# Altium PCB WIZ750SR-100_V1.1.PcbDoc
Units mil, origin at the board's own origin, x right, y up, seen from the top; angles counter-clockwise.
Board outline 1968.5 x 1181.1 mil, 4 copper layers (Top Layer, Internal Plane 1, Internal Plane 2, Bottom Layer); 76 components, 81 nets, 315 pads, 135 vias.
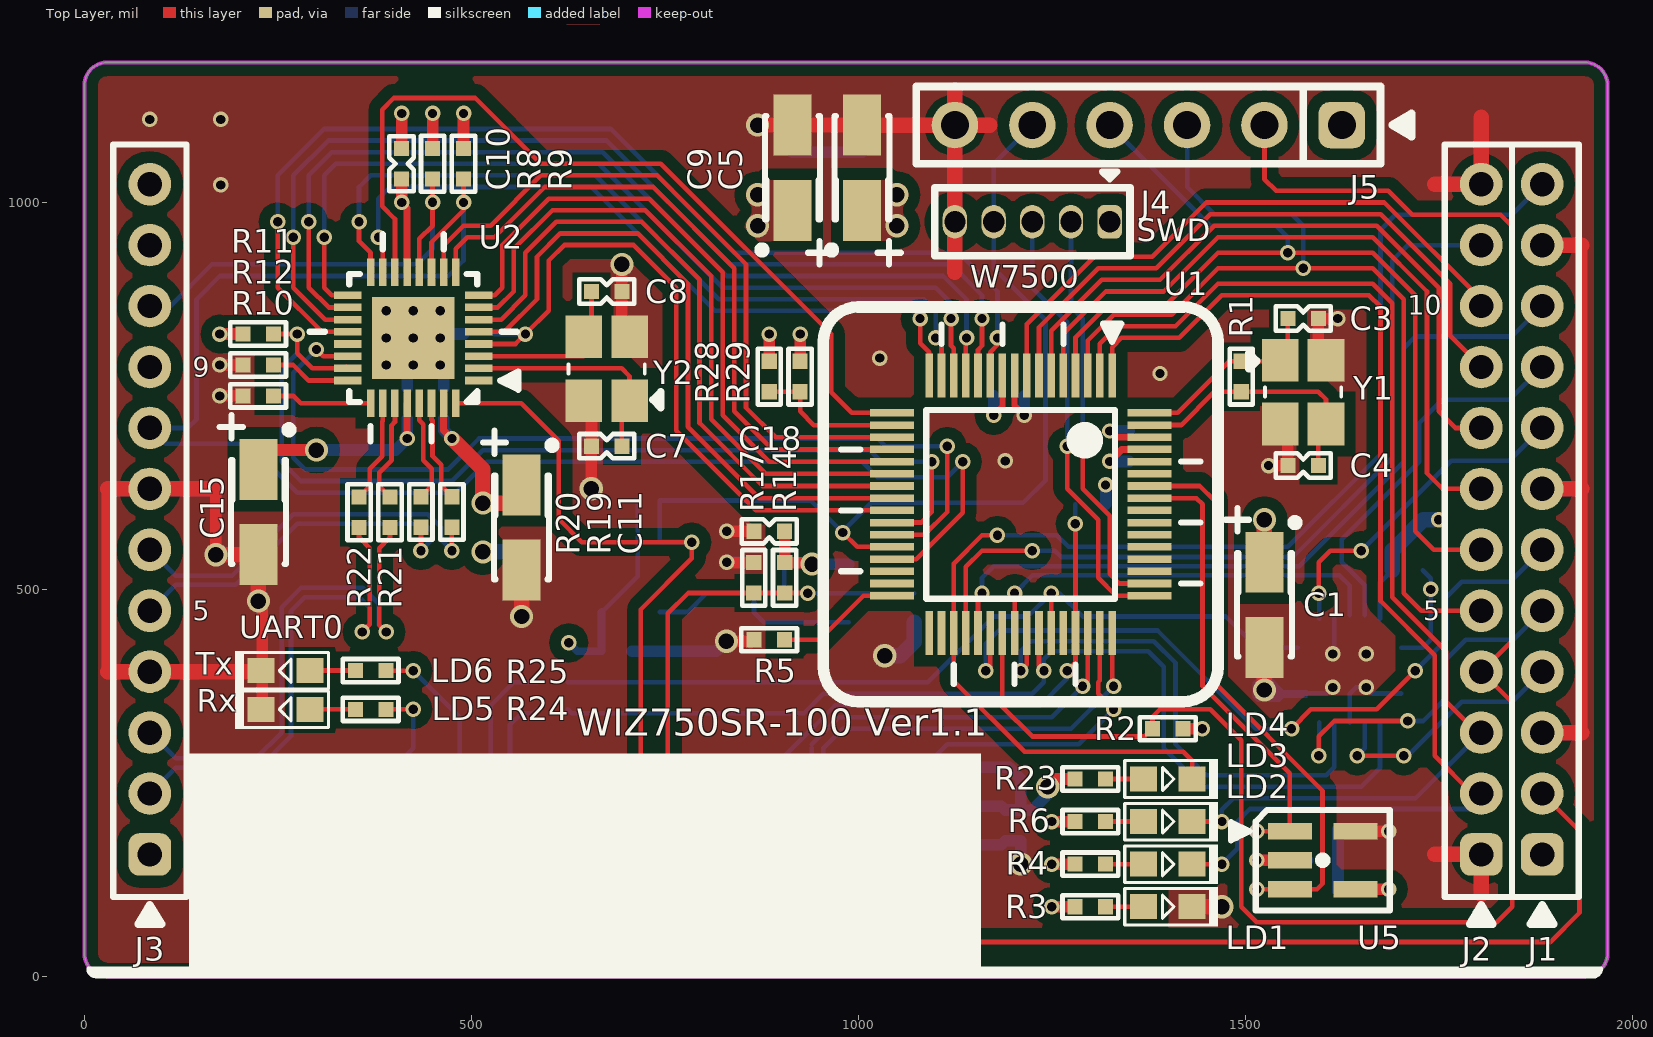
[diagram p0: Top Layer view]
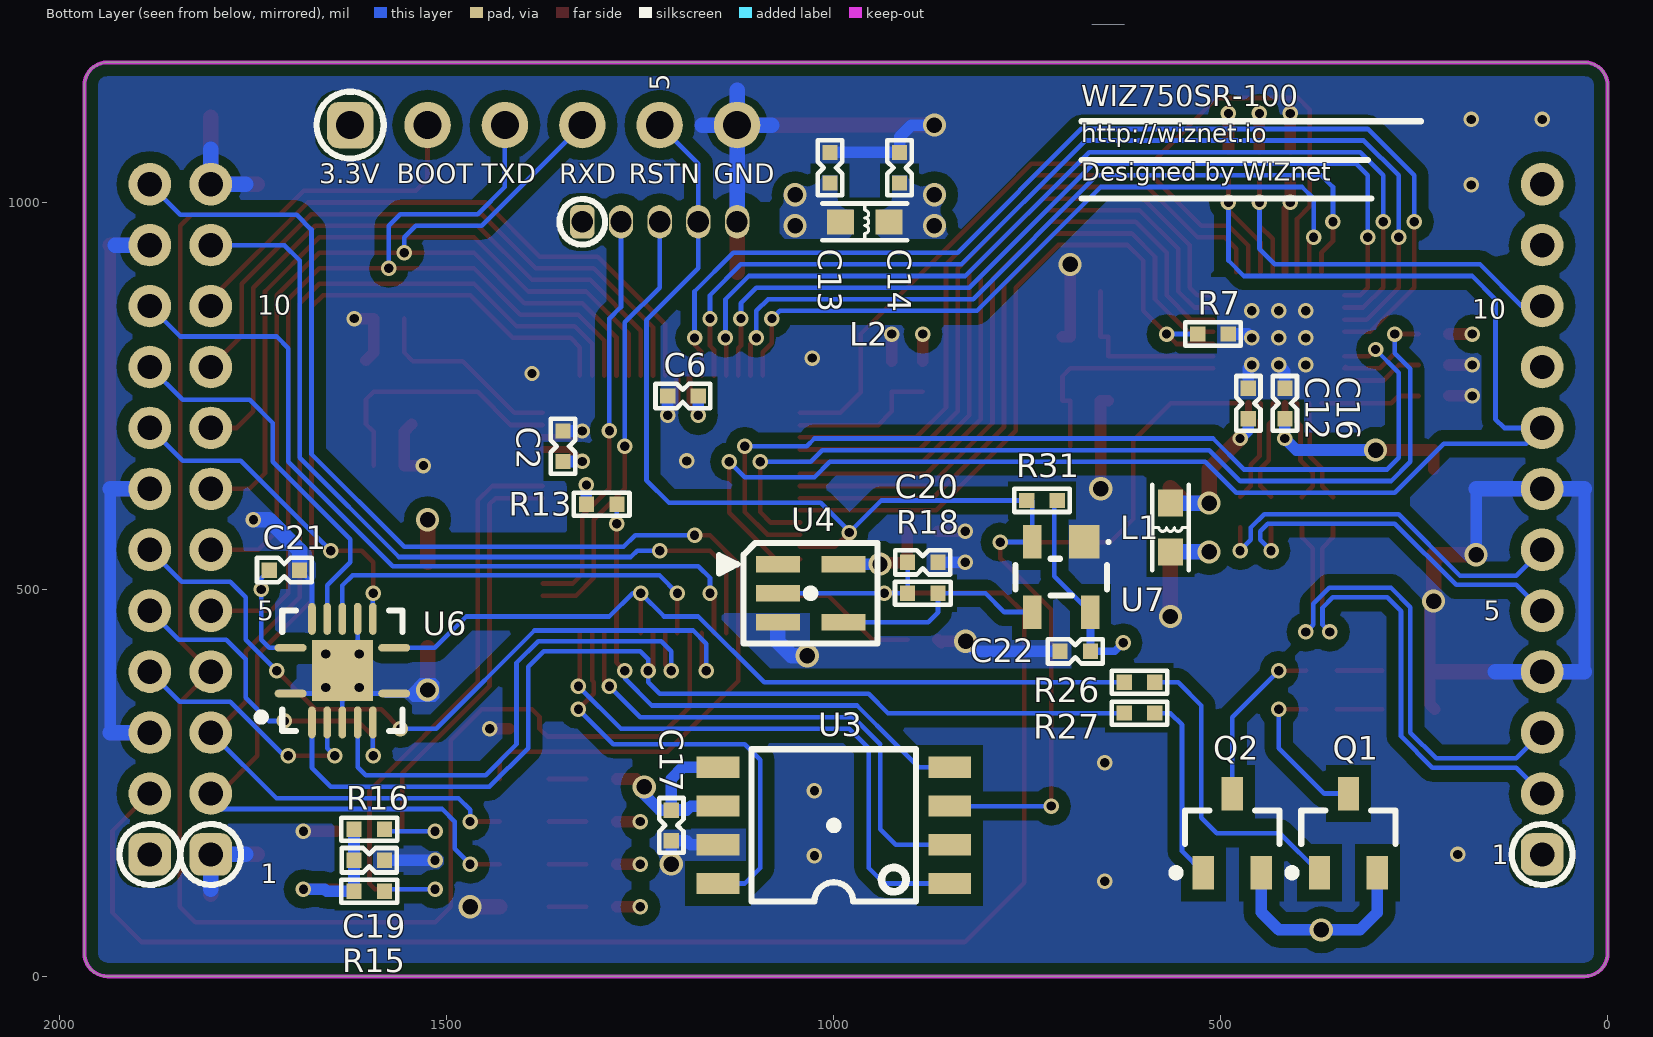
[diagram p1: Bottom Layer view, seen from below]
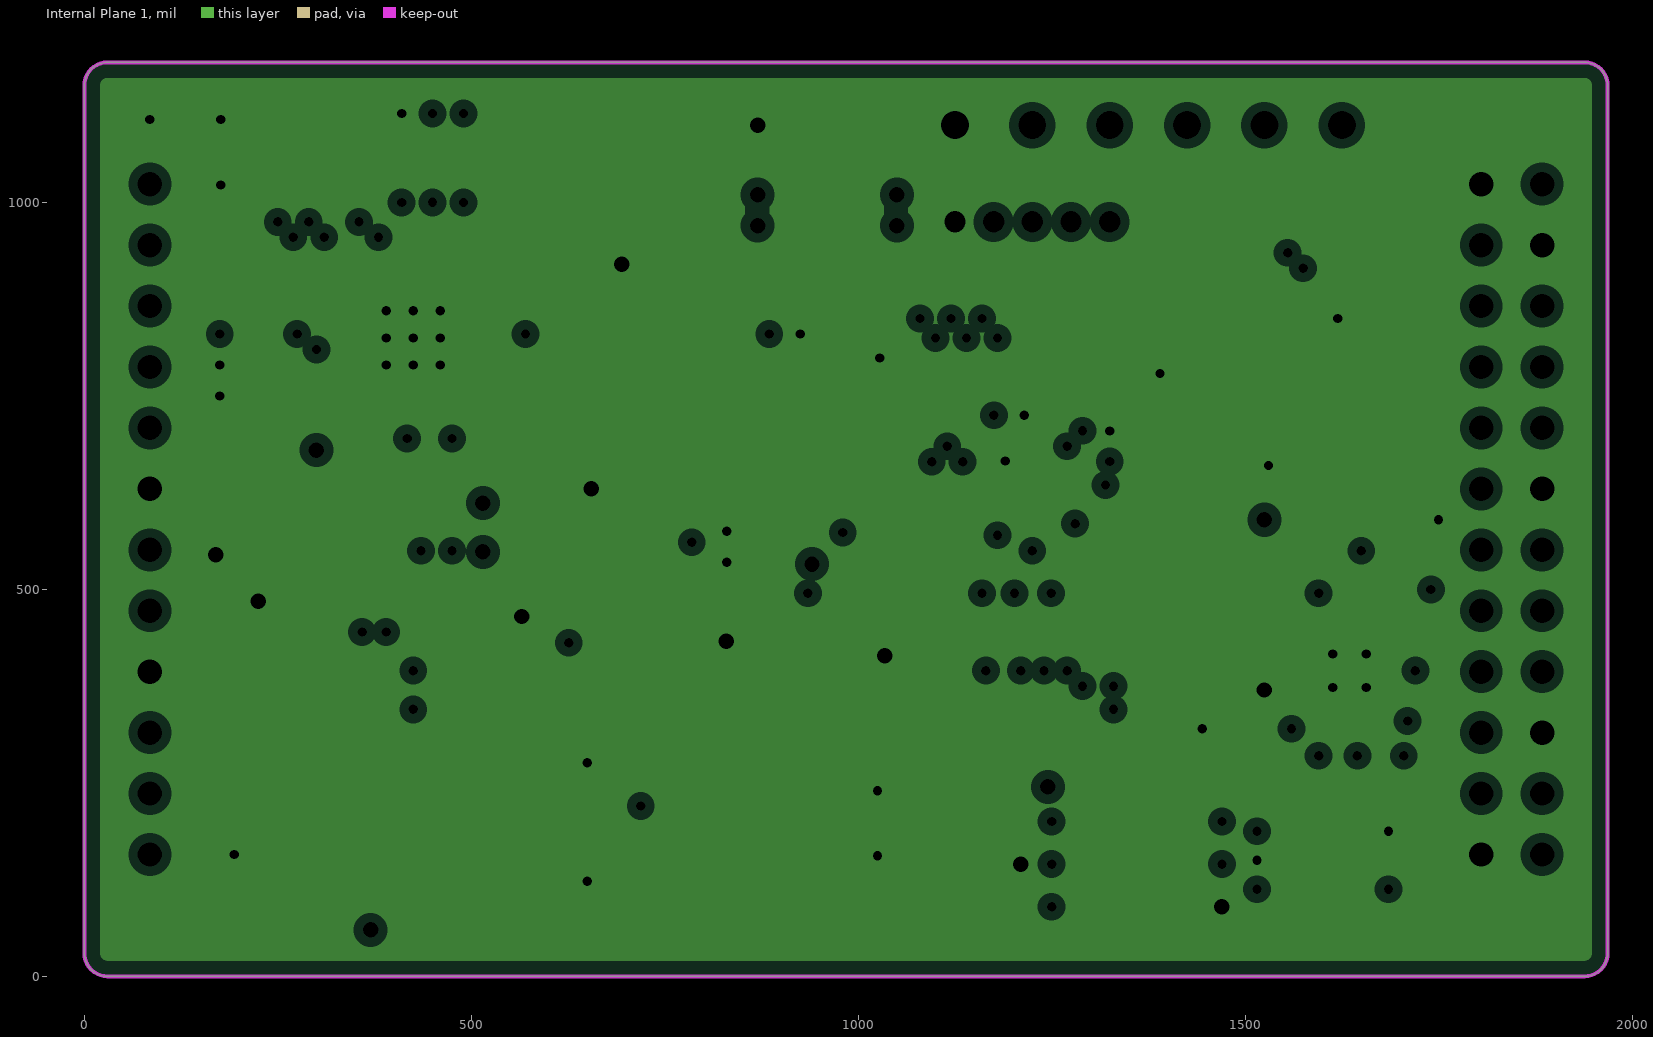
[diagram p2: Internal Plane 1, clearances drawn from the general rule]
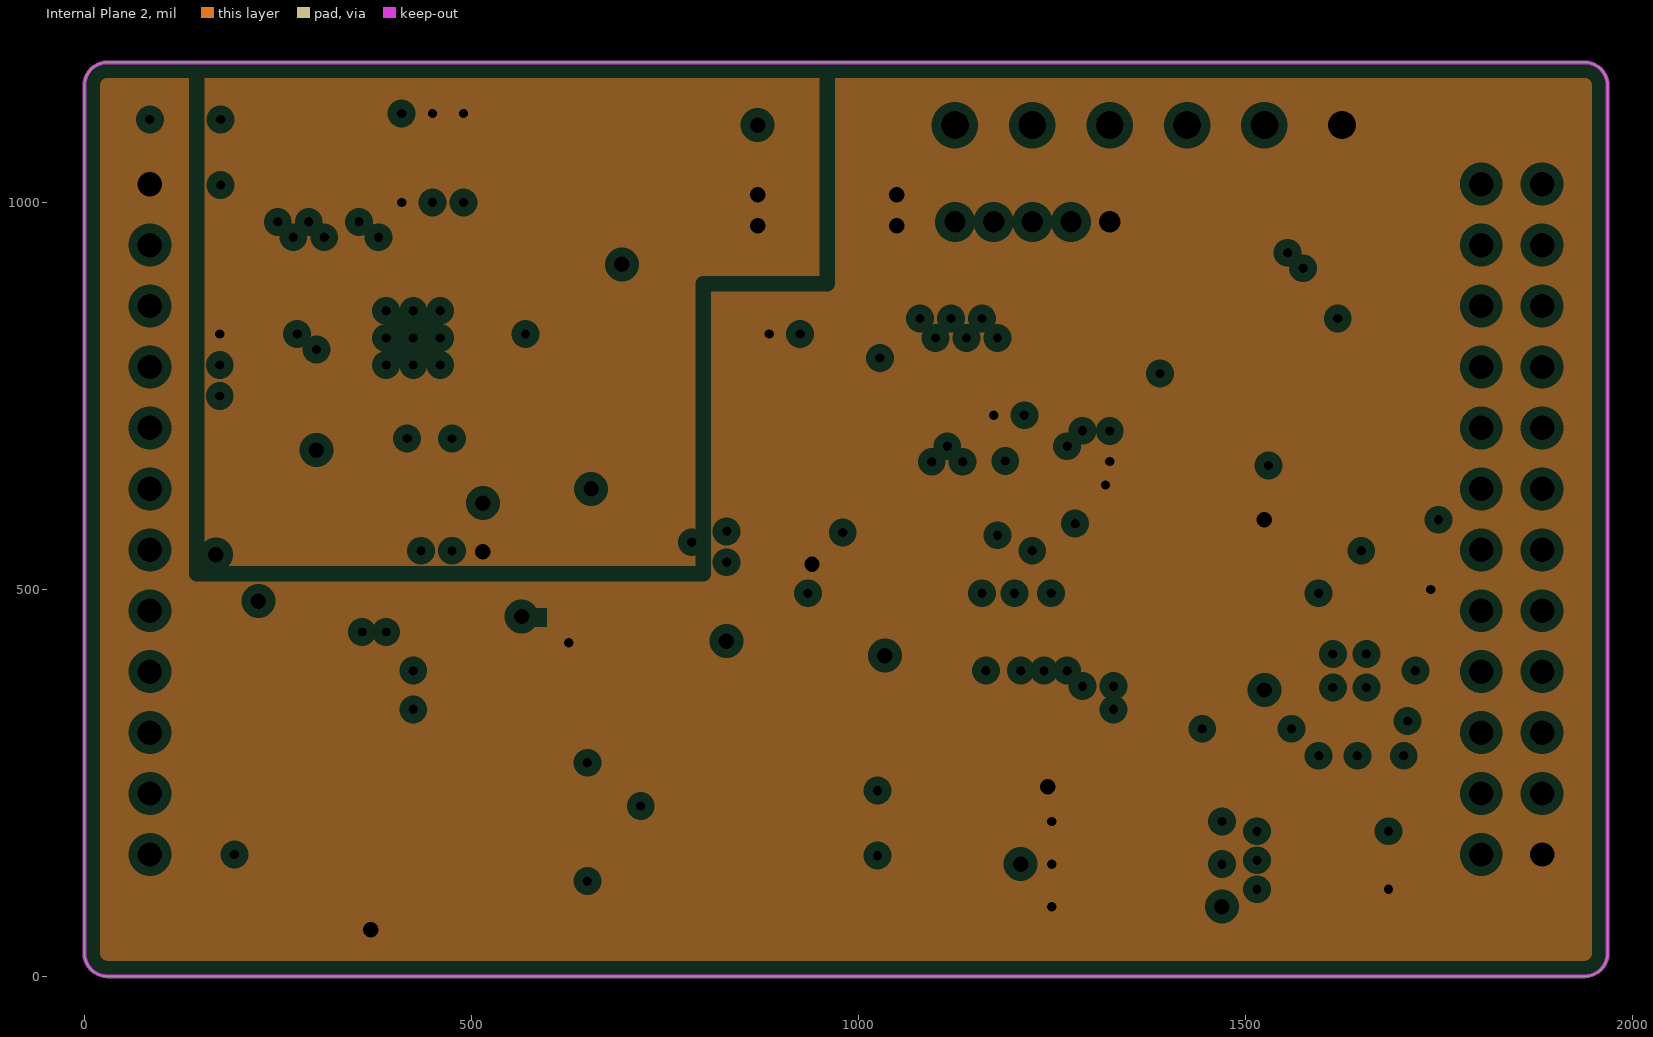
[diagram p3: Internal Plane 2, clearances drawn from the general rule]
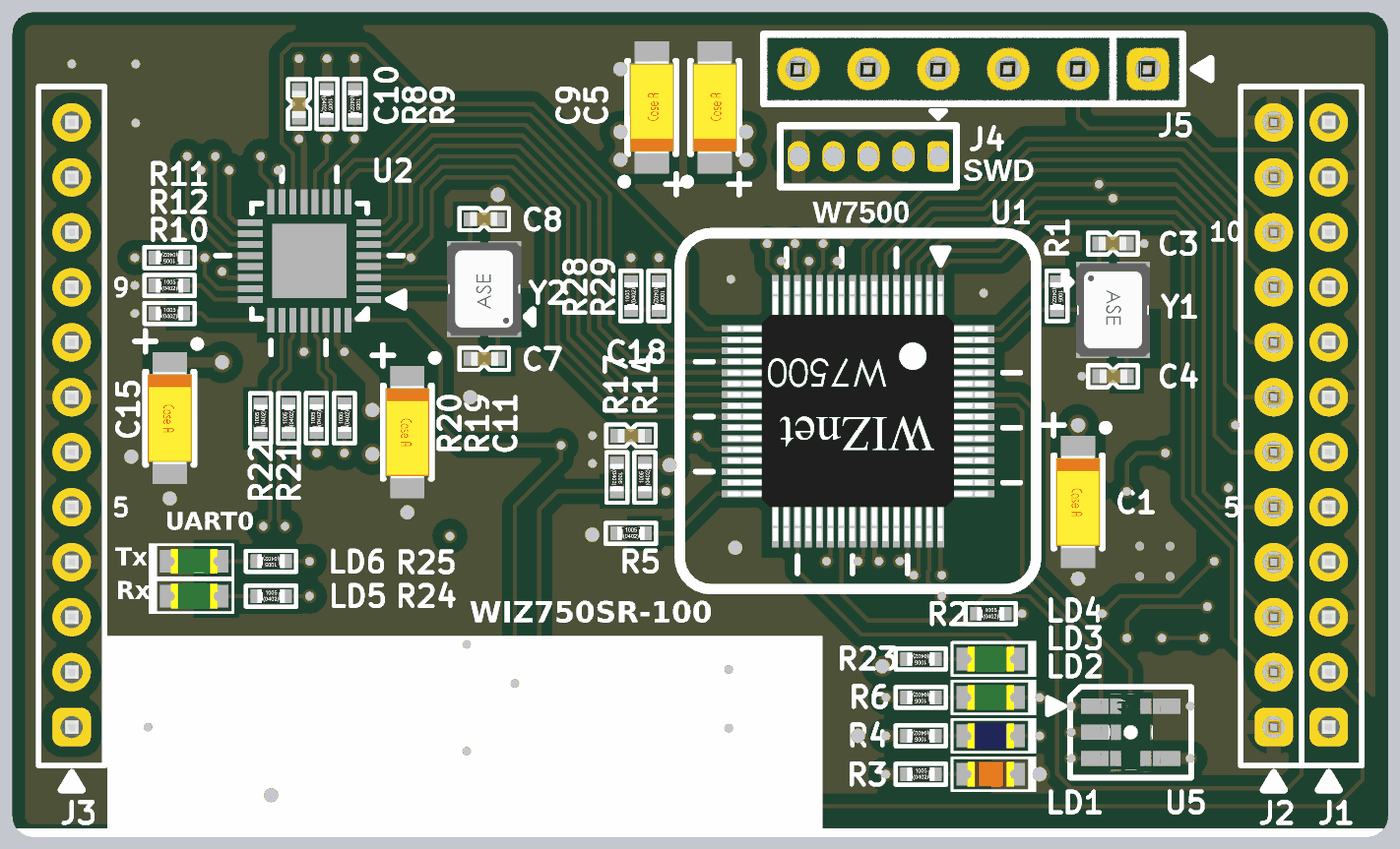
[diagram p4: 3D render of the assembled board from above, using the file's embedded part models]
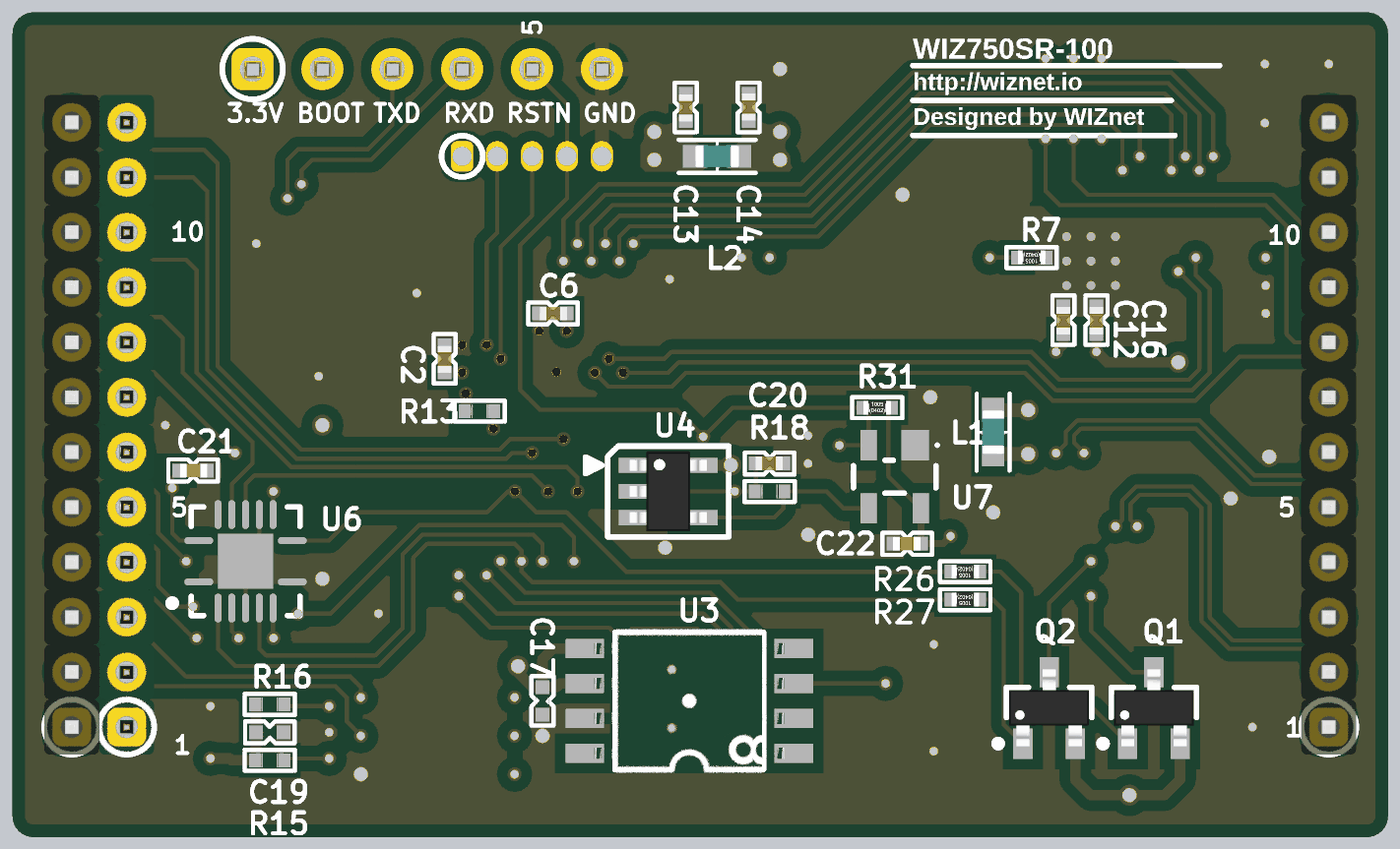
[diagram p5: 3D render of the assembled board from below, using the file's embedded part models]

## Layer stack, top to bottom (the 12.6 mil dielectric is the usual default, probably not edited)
Top Solder: solder mask 0.4, Solder Resist, Dk 3.5
Top Layer: signal copper 1.4
Dielectric1: core 12.6, FR-4, Dk 4.8
Internal Plane 1: plane copper 1.4, net GND
Dielectric5: prepreg 12.6, FR-4, Dk 4.8
Internal Plane 2: plane copper 1.4, net (Multiple Nets)
Dielectric6: core 12.6, FR-4, Dk 4.8
Bottom Layer: signal copper 1.4
Bottom Solder: solder mask 0.4, Solder Resist, Dk 3.5

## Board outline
0,30 0,1151.1 cw(c30,1151.1) 30,1181.1 1938.5,1181.1 cw(c1938.5,1151.1) 1968.5,1151.1 1968.5,30 cw(c1938.5,30) 1938.5,0 30,0 cw(c30,30)

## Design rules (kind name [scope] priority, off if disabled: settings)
Clearance [All] p1: gap=5.91 except(15: Arc-Poly Track-Poly SMDPad-Poly THPad-Poly Via-Poly Fill-Poly Poly-Poly Poly-Region)
DiffPairsRouting [All] p1: maxlimit=6 minlimit=6 mostfreqgap=6 toplayer_minwidth=6 toplayer_maxwidth=6 toplayer_prefwidth=6 bottomlayer_minwidth=6 bottomlayer_maxwidth=6 bottomlayer_prefwidth=6 maxuncoupledlength=600
HoleSize [All] p1: absolutevalues=TRUE maxlimit=160 minlimit=1 maxpercent=80.000 minpercent=20.000
PlaneClearance [All] p1: clearance=12
PlaneConnect [All] p1: planeconnectstyle=Direct reliefexpansion=20 reliefentries=4 reliefconductorwidth=10 reliefairgap=10
PolygonConnect PolygonConnect_2 [IsPad vs IsNamedPolygon('Top Layer-GND') Or  IsNamedPolygon('Bottom Layer-GND')] p1: connectstyle=Relief reliefconductorwidth=15 reliefentries=4 polygonreliefangle="90 Angle" airgapwidth=15
PolygonConnect PolygonConnect_1 [IsVia] p2: connectstyle=Direct reliefconductorwidth=10 reliefentries=4 polygonreliefangle="90 Angle" airgapwidth=10
PolygonConnect [All] p3: connectstyle=Direct reliefconductorwidth=10 reliefentries=4 polygonreliefangle="90 Angle" airgapwidth=10
RoutingVias [All] p1: holewidth=12 width=20 viastyle="Through Hole" minholewidth=12 minwidth=20 maxholewidth=20 maxwidth=30
SolderMaskExpansion [All] p1: expansion=0
Width [All] p1: maxlimit=20 minlimit=4 preferedwidth=5.98 minimp=50.000000 maximp=50.000000 favimp=50.000000
26 further rules are at their usual default settings.

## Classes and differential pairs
component class 1.WIZ750SR-100_W7500: C1 C2 C3 C4 C5 C6 LD1 LD2 LD3 LD4 LD5 LD6 Q1 Q2 R1 R2 R3 R4 R5 R6 R23 R24 R25 R26 R27 R28 R29 U1 Y1
component class 2.WIZ750SR_Transceiver: LD1 LD2 R41
differential pair MDI0_T: +MDI_T_P -MDI_T_N
differential pair MDI0_R: +MDI_R_P -MDI_R_N
differential pair MDI0_R: +MDI0_R_P -MDI0_R_N
differential pair MDI0_T: +MDI0_T_P -MDI0_T_N

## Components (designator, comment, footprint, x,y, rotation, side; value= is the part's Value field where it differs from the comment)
C1 "10uF/16V" "CAP-A Size" 1525,480 r270 top
C2 "1uF" CAP-0402#1 1350,685 r270 bottom
C3 "30pF" CAP-0402#1 1575,850 r180 top
C4 "30pF" CAP-0402#1 1575,660 r0 top
C5 "10uF/16V" "CAP-A Size" 1005,1045 r90 top
C6 "1uF" CAP-0402#1 1195,750 r180 bottom
C7 "27pF" CAP-0402#1 675,685 r0 top
C8 "27pF" CAP-0402#1 675,885 r180 top
C9 "10uF/16V" "CAP-A Size" 915,1045 r90 top
C10 "0.1uF" CAP-0402#1 410,1050 r270 top
C11 "10uF/16V" "CAP-A Size" 565,580 r270 top
C12 "0.1uF" CAP-0402#1 464.37,740.35 r270 bottom
C13 "0.1uF" CAP-0402#1 1005,1045 r270 bottom
C14 "0.1uF" CAP-0402#1 915,1045 r90 bottom
C15 "10uF/16V" "CAP-A Size" 225,600 r270 top
C16 "0.1uF" CAP-0402#1 417.13,740.35 r270 bottom
C17 "0.1uF(NM)" CAP-0402#1 1210,195 r270 bottom
C18 "0.1uF" CAP-0402#1 885,575 r0 top
C19 "0.1uF(NM)" CAP-0402#1 1600.32,150 r0 bottom
C20 "0.1uF" CAP-0402#1 885,535 r0 bottom
C21 "0.1uF" CAP-0402#2 1710,525 r180 bottom
C22 "0.1uF" CAP-0402#2 688,420 r0 bottom
J1 "2.00mm 1x12 Pin" IDC-1X12(2MM) 1883.86,157.48 r90 top locked
J2 "2.00mm 1x12 Pin(NM)" IDC-1X12(2MM) 1805.12,157.48 r90 top locked
J3 "2.00mm 1x12 Pin" IDC-1X12(2MM) 84.65,157.48 r90 top locked
J4 "1.27mm_1x5_Pin_header_DIP(NM)" IDC-1X5(1.27MM) 1325,975 r180 top
J5 "2.54mm 1x6 Pin Header DIP(NM)" IDC-1X6 1625,1100 r180 top locked
L1 "HH-1M1608-121JT" IND-0603 565,580 r270 bottom
L2 "HH-1M1608-121JT" IND-0603 960,975 r180 bottom
LD1 "RED-0603" LED-0603-RED 1400,90 r0 top
LD2 "BLUE-0603" LED-0603-BLUE 1400,145 r0 top
LD3 "GREEN-0603" LED-0603-GREEN 1400,200 r0 top
LD4 "GREEN-0603" LED-0603-GREEN 1400,255 r0 top
LD5 "GREEN-0603" LED-0603-GREEN 260,345 r180 top
LD6 "GREEN-0603" LED-0603-GREEN 260,395 r180 top
Q1 "Q-MMBT4403" Q-MMBT4403-SOT23 335,185 r90 bottom
Q2 "Q-MMBT4403" Q-MMBT4403-SOT23 485,185 r90 bottom
R1 "1M" RES-0402#1 1495,775 r270 top
R2 "4.7K" RES-0402#1 1400,320 r0 top
R3 "330R" RES-0402#1 1300,90 r0 top
R4 "1K" RES-0402#1 1300,145 r180 top
R5 "4.7K" RES-0402#1 885,435 r0 top
R6 "330R" RES-0402#1 1300,200 r180 top
R7 "5.1K" RES-0402#1 510,830 r0 bottom
R8 "5.1K" RES-0402#1 450,1050 r270 top
R9 "5.1K" RES-0402#1 490,1050 r270 top
R10 "6.19K / 1%" RES-0402#1 224.68,750 r0 top
R11 "5.1K" RES-0402#1 224.68,830 r180 top
R12 "5.1K" RES-0402#1 224.68,790 r0 top
R13 "4.7K(NM)" RES-0402#1 1300,610 r0 bottom
R14 "4.7K(NM)" RES-0402#1 905,515 r90 top
R15 "4.7K(NM)" RES-0402#1 1600.32,110 r0 bottom
R16 "4.7K(NM)" RES-0402#1 1600.32,190 r0 bottom
R17 "4.7K" RES-0402#1 865,515 r270 top
R18 "0R(NM)" RES-0402#1 885,495 r0 bottom
R19 "3.3R" RES-0402#1 475,600 r90 top
R20 "3.3R" RES-0402#1 435,600 r90 top
R21 "3.3R" RES-0402#1 395,599.69 r90 top
R22 "3.3R" RES-0402#1 355,599.69 r90 top
R23 "330R" RES-0402#1 1300,255 r180 top
R24 "330R" RES-0402#2 370,345 r0 top
R25 "330R" RES-0402#2 370,395 r180 top
R26 "1K" RES-0402#2 605,380 r0 bottom
R27 "1K" RES-0402#2 605,340 r0 bottom
R28 "4.7K/NC" RES-0402#2 885,775 r90 top
R29 "4.7K" RES-0402#2 925,775 r270 top
R31 "4.7K" RES-0402#2 731,615 r180 bottom
U1 "W7500" W7500-LQFP64 1210,610 r270 top locked
U2 "IP101GR/GRI" QFN32(0.4/4X4) 425,825 r180 top locked
U3 "AT45DB161E-SHF-T" SO-08-EIAJ 1000,195 r0 bottom
U4 "SN74LVC1G04DBVR" SOT-23-5L 1030,495 r180 bottom
U5 "24AA16T-I/OT" SOT-23-5L 1600.32,150 r0 top
U6 "SN74LVC125A" SN74LVC125A 1635,395 r180 bottom
U7 "MIC811SUY" MIC811SUY/SOT-143 706,516 r270 bottom
Y1 "12MHz" OSC-TZ1067B 1575,755 r270 top
Y2 "25MHz" OSC-82J0626 675,785 r90 top

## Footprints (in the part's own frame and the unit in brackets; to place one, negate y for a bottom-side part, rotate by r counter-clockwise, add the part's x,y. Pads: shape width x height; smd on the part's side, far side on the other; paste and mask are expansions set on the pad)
CAP-0402#1 [mm]
  rect 0.5x0.5 smd: 1(-0.5,0) 2(0.5,0)
  silkscreen extent -0.9,-0.4 0.9,0.4, body extent -0.48,-0.25 0.52,0.25, height 0.6
CAP-0402#2 [mm] "Ceramic CAP 0402(1005)"
  rect 0.5x0.5 smd: 1(-0.5,-0.004) 2(0.5,-0.004)
  silkscreen extent -0.9,-0.4 0.9,0.4, body extent -0.48,-0.25 0.52,0.25, height 0.6
"CAP-A Size" [mm] "Tantal CAP A Size EIA/IECQ 3216"
  rect 2x1.25 smd: 1(-1.4,0) 2(1.4,0)
  silkscreen extent -3.17,-1.27 1.7,1.12, body extent -1.7,-0.8 1.7,0.8, height 1.75
IDC-1X5(1.27MM) [mm]
  rrect50% 0.8x1.1 hole 0.7: 1(0,0)
  oval 0.8x1.1 hole 0.7: 2(1.27,0) 3(2.54,0) 4(3.81,0) 5(5.08,0)
  silkscreen extent -0.66,-1.65 5.74,1.11
IDC-1X6 [mil] "6-Way 2.54 mm Male Header"
  rrect50% 60x60 hole 36: 1(0,0)
  round 60 hole 36: 2(100,0) 3(200,0) 4(300,0) 5(400,0) 6(500,0)
  silkscreen extent -90,-50 550,50, body extent -49,-49 551,51, height 336
IDC-1X12(2MM) [mil]
  rrect50% 55x55 hole 31.5: 1(0,0)
  round 55 hole 31.5: 2(78.74,0) 3(157.48,0) 4(236.22,0) 5(314.96,0) 6(393.7,0) 7(472.44,0) 8(551.18,0) 9(629.92,0) 10(708.66,0) 11(787.4,0) 12(866.14,0)
  silkscreen extent -90,-47 917,39, body extent -39,-39 906,39, height 217
IND-0603 [mm] "Inductor 0603(1608)"
  rect 0.89x0.82 smd: 1(-0.8,0) 2(0.8,0)
  silkscreen extent -1.4,-0.6 1.4,0.6, body extent -0.8,-0.4 0.8,0.4, height 0.95
LED-0603-BLUE [mm] "LED-0603-BLUE"
  rect 0.89x0.82 smd: 1(-0.8,0) 2(0.8,0)
  silkscreen extent -1.41,-0.65 1.65,0.65, body extent -0.85,-0.45 0.85,0.45, height 0.9
LED-0603-GREEN [mm] "LED-0603-GREEN"
  rect 0.89x0.82 smd: 1(-0.8,0) 2(0.8,0)
  silkscreen extent -1.41,-0.65 1.65,0.65, body extent -0.85,-0.45 0.85,0.45, height 0.9
LED-0603-RED [mm] "LED-0603-RED"
  rect 0.89x0.82 smd: 1(-0.8,0) 2(0.8,0)
  silkscreen extent -1.41,-0.65 1.65,0.65, body extent -0.85,-0.45 0.85,0.45, height 0.9
MIC811SUY/SOT-143 [mm] "SOT143, 4-Leads, Body 2.92x2.37mm, Pitch 1.90mm, IPC Medium Density"
  rect 1.1x1 smd: 1(-1.15,0.75)
  rect 1.1x0.6 smd: 2(-1.15,-0.95) 3(1.15,-0.95) 4(1.15,0.95)
  silkscreen extent -1.2,-1.5 0.6,1.6, body extent -0.6,-1.52 0.6,1.52, height 1.2
OSC-82J0626 [mm]
  rect 1.4x1.2 smd: 1(-1.05,-0.75) 2(1.05,-0.75) 3(1.05,0.75) 4(-1.05,0.75)
  silkscreen extent -1.27,-1.78 0.15,1.25, body extent -1.7,-1.35 1.7,1.35, height 1.06
OSC-TZ1067B [mm]
  rect 1.4x1.2 smd: 1(-1.05,-0.75) 2(1.05,-0.75) 3(1.05,0.75) 4(-1.05,0.75)
  silkscreen extent -1.27,-1.78 0.15,1.25, body extent -1.7,-1.35 1.7,1.35, height 1.06
Q-MMBT4403-SOT23 [mm] "PNP General-Purpose Amplifier"
  rect 1.1x0.7 smd: 1(-1.3,0.95) 2(-1.3,-0.95) 3(1.3,0)
  silkscreen extent -1.42,-1.55 0.75,1.98, body extent -1.4,-1.45 1.4,1.45, height 1.3
QFN32(0.4/4X4) [mm]
  rect 0.9x0.25 smd: 1(-2.15,1.4) 2(-2.15,1) 3(-2.15,0.6) 4(-2.15,0.2) 5(-2.15,-0.2) 6(-2.15,-0.6) 7(-2.15,-1) 8(-2.15,-1.4) 17(2.15,-1.4) 18(2.15,-1) 19(2.15,-0.6) 20(2.15,-0.2) 21(2.15,0.2) 22(2.15,0.6) 23(2.15,1) 24(2.15,1.4)
  rect 0.25x0.9 smd: 9(-1.4,-2.15) 10(-1,-2.15) 11(-0.6,-2.15) 12(-0.2,-2.15) 13(0.2,-2.15) 14(0.6,-2.15) 15(1,-2.15) 16(1.4,-2.15) 25(1.4,2.15) 26(1,2.15) 27(0.6,2.15) 28(0.2,2.15) 29(-0.2,2.15) 30(-0.6,2.15) 31(-1,2.15) 32(-1.4,2.15)
  rect 2.7x2.7 smd: 33(0,0)
  silkscreen extent -3.45,-3.4 3.4,3.4, body extent -2.1,-2.1 2.1,2.1, height 0.76
RES-0402#1 [mm]
  rect 0.5x0.5 smd: 1(-0.5,0) 2(0.5,0)
  silkscreen extent -0.91,-0.38 0.91,0.38, body extent -0.5,-0.25 0.5,0.25, height 0.35
RES-0402#2 [mm]
  rect 0.5x0.5 smd: 1(-0.5,-0.004) 2(0.5,-0.004)
  silkscreen extent -0.91,-0.38 0.91,0.38, body extent -0.5,-0.25 0.5,0.25, height 0.35
SN74LVC125A [mm] "QFN, 14-Leads, Body 3.50x3.50mm, Pitch 0.50mm/1.50mm, Thermal Pad 2.00x2.00mm, IPC Low Density"
  oval 1.05x0.25 smd: 1(-1.7,-0.75) 7(1.7,-0.75) 8(1.7,0.75) 14(-1.7,0.75)
  oval 0.25x1.05 smd: 2(-1,-1.7) 3(-0.5,-1.7) 4(0,-1.7) 5(0.5,-1.7) 6(1,-1.7) 9(1,1.7) 10(0.5,1.7) 11(0,1.7) 12(-0.5,1.7) 13(-1,1.7)
  rect 2x2 smd: 15(0,0)
  silkscreen extent -2.79,-1.97 1.97,1.97, body extent -1.83,-1.83 1.83,1.83, height 1
SO-08-EIAJ [mm]
  rect 1.4x0.7 smd: 1(-3.8,1.905) 2(-3.8,0.635) 3(-3.8,-0.635) 4(-3.8,-1.905) 5(3.8,-1.905) 6(3.8,-0.635) 7(3.8,0.635) 8(3.8,1.905)
  silkscreen extent -2.7,-2.5 2.7,2.5, body extent -4,-2.63 4,2.63, height 2.58
SOT-23-5L [mm]
  rect 1.45x0.55 smd: 1(-1.075,0.95) 2(-1.075,0) 3(-1.075,-0.95) 4(1.075,-0.95) 5(1.075,0.95)
  silkscreen extent -3.01,-1.65 2.2,1.65, body extent -1.4,-1.45 1.4,1.45, height 1.45
W7500-LQFP64 [mm] "WIZnet ARM Cortex-M0, LQFP64, Pitch 0.40mm"
  rect 1.45x0.25 smd: 1(-4.225,3) 2(-4.225,2.6) 3(-4.225,2.2) 4(-4.225,1.8) 5(-4.225,1.4) 6(-4.225,1) 7(-4.225,0.6) 8(-4.225,0.2) 9(-4.225,-0.2) 10(-4.225,-0.6) 11(-4.225,-1) 12(-4.225,-1.4) 13(-4.225,-1.8) 14(-4.225,-2.2) 15(-4.225,-2.6) 16(-4.225,-3) 33(4.225,-3) 34(4.225,-2.6) 35(4.225,-2.2) 36(4.225,-1.8) 37(4.225,-1.4) 38(4.225,-1) 39(4.225,-0.6) 40(4.225,-0.2) 41(4.225,0.2) 42(4.225,0.6) 43(4.225,1) 44(4.225,1.4) 45(4.225,1.8) 46(4.225,2.2) 47(4.225,2.6) 48(4.225,3)
  rect 0.25x1.45 smd: 17(-3,-4.225) 18(-2.6,-4.225) 19(-2.2,-4.225) 20(-1.8,-4.225) 21(-1.4,-4.225) 22(-1,-4.225) 23(-0.6,-4.225) 24(-0.2,-4.225) 25(0.2,-4.225) 26(0.6,-4.225) 27(1,-4.225) 28(1.4,-4.225) 29(1.8,-4.225) 30(2.2,-4.225) 31(2.6,-4.225) 32(3,-4.225) 49(3,4.225) 50(2.6,4.225) 51(2.2,4.225) 52(1.8,4.225) 53(1.4,4.225) 54(1,4.225) 55(0.6,4.225) 56(0.2,4.225) 57(-0.2,4.225) 58(-0.6,4.225) 59(-1,4.225) 60(-1.4,4.225) 61(-1.8,4.225) 62(-2.2,4.225) 63(-2.6,4.225) 64(-3,4.225)
  silkscreen extent -6.48,-6.48 6.48,6.48, body extent -4.73,-4.74 4.73,4.72, height 1

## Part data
C1 C5 C9 C11 C15: library part "CAP-A Size", "Tantla CAP A Size EIA/IECQ 3216"
C2 C3 C4 C6 C7 C8 C10 C12 C13 C14 C16 C17 C18 C19 C20 C21 C22: library part CAP-0402, "Ceramic CAP 0402(1005)"
J1 J2 J3: library part "Header 1x12 (2.00mm)", "pin header 2.00mm 1x12"
J4: library part 1.27mm_1x5_Pin_header_DIP, "1.27mm_1x5_Pin_header_DIP"
J5: library part "Header 6", "Header, 6-Pin"
L1 L2: library part IND-0603, "Inductor 0603(1608)"
LD1 LD2 LD3 LD4 LD5 LD6: library part LED-0603, "LED-0603"
Q1 Q2: "PNP General-Purpose Amplifier"
R1 R2 R3 R4 R5 R6 R7 R10 R11 R12 R13 R14 R15 R16 R17 R18 R19 R20 R21 R22 R23 R24 R25 R26 R27 R28 R29 R31: library part RES-0402, "RES-0402"
R8 R9: library part RES-0603, "RES-0402"
U1: "WIZnet ARM Cortex-M0"
U3: "16-Mbit DataFlash, 2.3V or 2.5V Minimum SPI Serial Flash Memory"
U4: "IC, INVERTER, SINGLE, SMD, SOT-23-5"
U5: library part 24AAxxT-i-OT, "SOT-23"
U6: "Quadruple Bus Buffer Gate With 3-State Outputs"
U7: "Microprocessor Reset Circuits"
Y1: library part OSC-TZ1067B-12MHz, "X-tal 12MHz,3.2x2.5 SMD, CL=20pF"
Y2: library part OSC-82J0626-25MHz, "X-tal 25MHz,3.2x2.5 SMD, CL=18pF"

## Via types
v1: diameter 20, hole 12, Top Layer to Bottom Layer, tented both sides, 109 vias
v2: diameter 30, hole 20, Top Layer to Bottom Layer, tented both sides, 22 vias
v3: diameter 20, hole 12.01, Top Layer to Bottom Layer, tented both sides, 4 vias

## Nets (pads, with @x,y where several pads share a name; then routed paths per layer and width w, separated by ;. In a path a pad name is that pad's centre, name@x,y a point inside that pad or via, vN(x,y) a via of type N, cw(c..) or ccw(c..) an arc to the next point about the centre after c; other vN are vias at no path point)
APP_BOOT: J2.11 U1.36 | length 1079.8
  Top Layer w6: U1.36 1139.13,529.13 1160,550 v1(1225,550)
  Bottom Layer w5.98: 1254.13,550 1262.23,541.9 1272.96,541.9 1561.9,541.9 1690,670
  Bottom Layer w6: v1(1225,550) 1254.13,550 ; 1690,670 1690,925 1709.88,944.88 J2.11
BOOT: J2.4 J5.2 R2.1 U1.39 | length 2368.3
  Top Layer w6: U1.39 1186.38,348.62 1225,310 1370.32,310 R2.1 1380.32,335.31 1390,345 1455,345 1495,305 1495,90 1515,70 1825,70 1845,90 1845,353.82 J2.4 1844.49,433.07 1844.49,969.76 1830,984.25 1715.75,984.25 1685,1015 1540,1015 1525,1030 J5.2
DUP: R28.1 R29.2 U1.18 | length 191.1
  Top Layer w5.98: R28.1 925,755.32 925,730 942.64,712.36 U1.18
EX_RESET: C20.2 J1.2 R14.1 R17.2 R18.2 U4.2 | length 2147.3
  Top Layer w6: v1(935,495) 934.68,495.31 R14.1 R17.2 780.32,495.31 754,469 754,121 830.71,44.29 1894.29,44.29 1932.09,82.09 1932.09,187.99 J1.2
  Bottom Layer w6: C20.2 R18.2 v1(935,495) U4.2
EXPANSION_GPIO_A: J2.10 U1.8 | length 779.4
  Top Layer w6: U1.8 1217.87,842.87 1305,930 1380,930 1450,1000 1680,1000 1805.12,874.88 J2.10
EXPANSION_GPIO_B: J2.9 U1.7 | length 815.8
  Top Layer w6: U1.7 1233.62,838.62 1310,915 1385,915 1455,985 1675,985 1765,895 1765,827.52 J2.9
EXPANSION_GPIO_C: J2.8 U1.6 | length 871.9
  Top Layer w6: U1.6 1249.37,834.37 1315,900 1390,900 1460,970 1670,970 1750,890 1750,730 1771.34,708.66 J2.8
EXPANSION_GPIO_D: J2.7 U1.5 | length 917.8
  Top Layer w6: U1.5 1265.12,830.12 1320,885 1395,885 1465,955 1665,955 1735,885 1735,650 1755.08,629.92 J2.7
GND: C1.2 C2.1 C3.1 C4.1 C5.2 C6.1 C7.1 C8.1 C9.2 C10.1 C11.2 C12.1 C13.1 C14.2 C15.2 C16.1 C17.2 C18.1 C19.1 C20.1 C21.2 C22.2 J1.3 J1.7 J1.11 J2.1 J2.12 J3.4 J3.7 J4.5 J5.6 LD1.2 LD5.2 LD6.2 R2.2 R5.1 R7.1 R10.1 R12.1 R17.1 R29.1 U1.9 U1.62 U2.33 U3.7 U4.3 U5.2 U5.5 U6.1 U6.4 U6.7 U6.10 U6.13 U6.15 U7.1 Y1.2 Y1.4 Y2.2 Y2.4 | length 6094
  Top Layer w8: U1.9 1202.13,737.56 v1(1214.68,725)
  Top Layer w9: v1(1325,704.68) 1333.07,696.61 U1.62
  Top Layer w15: 30,393.7 30,629.92 ; v2(170,544.88) 170,629.92 ; v1(175,750) R10.1 ; v1(175,790) R12.1 ; LD5.2@223.5,345 230,351.5 230,480 v2(225,485) ; C10.1 v1(410,1115) ; Y2.4 655.32,743.66 C7.1 655,684.68 v2(655,630) ; v2(694.68,920) C8.1 694.68,826.34 Y2.2 ; v2(829.72,433.07) 859.45,433.07 861.42,431.1 R5.1 ; v1(830,535) 830.32,534.69 R17.1 ; v1(830,575) C18.1 ; R29.1@925,794.68 v1(925,830) ; R2.2 v1(1444.68,320) ; v1(1515.32,150) U5.2 ; v1(1530.32,660) C4.1 1555.32,703.82 Y1.2 ; Y1.4 1594.68,806.18 C3.1 v1(1619.68,850) ; U5.5 v1(1685.32,187.4) ; 1935,314.96 1935,629.92 1935,944.88
  Top Layer w20: 30,393.7 J3.4 LD6.2@225,393.7 ; 30,629.92 J3.7 170,629.92 ; v2(170,544.88) C15.2 v2(225,485) ; v2(565,465) C11.2@565,544.88 ; v2(870,1100) 865,1100 865.12,1100.12 C9.2 C5.2 ; C5.2@1005,1100 J5.6 ; 1125,910 J4.5 J5.6 ; 1125,1145 J5.6 ; 1170,1100 J5.6 ; LD1.2 v2(1470,90) ; v2(1525,370) C1.2 ; 1745,157.48 J2.1 1805.12,106.3 ; 1745,1023.62 J2.12 1805.12,1110 ; J1.3 1935,314.96 ; J1.7 1935,629.92 ; J1.11 1935,944.88
  Bottom Layer w5.98: U6.7 1605.47,365.47 v3(1613.35,373.35) ; v3(1613.35,416.65) 1615.31,418.62 U6.10 ; U6.4 1635,365 1643.35,373.35 v3(1656.65,373.35) 1664.53,365.47 U6.1 ; U6.13 1674.37,508.9 C21.2
  Bottom Layer w15: 30,393.7 30,629.92 ; v2(170,544.88) 170,629.92 ; C16.1 417.13,782.13 v1(425,790) ; v1(460,790) 464.37,785.63 C12.1 ; v1(460,825) 465,830 R7.1 ; C22.2 816.81,420.16 v2(829.72,433.07) ; v1(830,535) C20.1 ; v2(870,1100) 900,1100 915,1085 C14.2 C13.1 ; U3.7 1185,170 1190.32,175.31 C17.2 v2(1210,145) ; v1(1214.68,725) C6.1 ; v1(1325,704.68) C2.1 ; v1(1515.32,150) C19.1 ; 1935,314.96 1935,629.92
  Bottom Layer w20: 30,393.7 J3.4 145,393.7 ; 30,629.92 J3.7 170,629.92 ; v2(1034.45,414.37) 1054.53,414.37 1072.32,432.17 U4.3 ; 1080,1100 J5.6 ; J4.5 J5.6 ; 1125,1145 J5.6 ; 1170,1100 J5.6 ; C21.2 1690.32,550.31 1730,590 v1(1750,590) ; 1760.12,157.48 J2.1 1805.12,112.48 ; 1760.12,1023.62 J2.12 1805.12,1068.62 ; J1.3 1935,314.96 ; J1.7 1935,629.92 ; J1.11 1928.86,944.88
  other v1: 650,123 1025,156 193.9,157.48 1025,240 650,276 1190,666 1390,779 390,790 1028,799 390,825 425,825 390,860 425,860 460,860 176.18,1022.64 84.65,1107.28 176.18,1107.28
  other v3: 1656.65,416.65
IN_CTS: J1.9 U6.12 | length 490.6
  Bottom Layer w5.98: U6.12@1654.68,466.93 1654.68,505.31 1625,535 1625,565 1725,665 1725,715 1755,745 1789.98,745 1790.04,745.06 1841.52,745.06 J1.9
IN_RXD: J1.8 U6.9 | length 434.1
  Top Layer w5.98: v1(1595,495) 1595,535 1610,550 v1(1650,550)
  Bottom Layer w5.98: v1(1595,495) 1595.63,494.37 U6.9 ; v1(1650,550) 1766.32,666.32 1841.52,666.32 J1.8
IP_3.3A: C11.1 C12.2 L1.1 U2.31 | length 288.2
  Top Layer w9: U2.31 464.37,705.63 v1(475,695)
  Top Layer w20: v1(475,695) 515,655 v2(515,611.5) 545,611.5 C11.1@565,631.5
  Bottom Layer w15: C12.2 464.37,705.63 v1(475,695)
  Bottom Layer w20: v2(515,611.5) L1.1
IP_3.3V: C9.1 C10.2 C14.1 L1.2 L2.2 R8.1 R9.1 R11.2 U2.13 | length 294.3
  Top Layer w9: v1(410,1000) 417.13,992.87 U2.13
  Top Layer w15: v1(175,830) R11.2 ; v1(410,1000) C10.2 ; R8.1 v1(450,1115) ; R9.1 v1(490,1115)
  Bottom Layer w20: v2(515,548.5) L1.2
  other v2: 870,970 870,1010
MDI0_R_N: R22.2 U2.26 | length 133.7
  Top Layer w6: R22.2 369,633.37 369,655.97 385,671.97 385,716.97 385.63,717.6 U2.26
MDI0_R_P: R21.2 U2.27 | length 135.2
  Top Layer w6: R21.2 381,633.37 381,651 397,667 397,712 401.38,716.38 U2.27
MDI0_T_N: R20.2 U2.29 | length 133.1
  Top Layer w6: U2.29 432.87,718.42 438,713.29 438,667 449,656 449,633.68 R20.2
MDI0_T_P: R19.2 U2.30 | length 131.6
  Top Layer w6: U2.30 448.62,719.64 450,718.26 450,671.97 461,660.97 461,633.68 R19.2
MDI_R_N: J3.2 R22.1 | length 669.8
  Top Layer w6: R22.1 355,567.16 369,553.16 369,455 v1(359,445)
  Bottom Layer w6: J3.2 118.02,269.59 226.56,269.59 267,310.03 267,472 285,490 355,490 368.5,476.5 368.5,454.5 v1(359,445)
MDI_R_P: J3.3 R21.1 | length 689.3
  Top Layer w6: v1(390,445) 381,454 381,553.16 395,567.16 R21.1
  Bottom Layer w6: J3.3 118.02,281.59 221.59,281.59 255,315 255,476.97 280.03,502 359.97,502 380.5,481.47 380.5,454.5 v1(390,445)
MDI_T_N: J3.5 R20.1 | length 476.2
  Top Layer w6: v1(435,550) R20.1
  Bottom Layer w6: J3.5 118.02,505.81 195.81,505.81 275,585 439,585 449,575 449,564 v1(435,550)
MDI_T_P: J3.6 R19.1 | length 496.1
  Top Layer w6: v1(475,550) R19.1
  Bottom Layer w6: J3.6 118.02,517.81 190.84,517.81 270.03,597 443.97,597 461,579.97 461,564 v1(475,550)
NetC15_1: C15.1 C16.2 U2.28 | length 294.3
  Top Layer w9: v1(417.13,695) U2.28
  Top Layer w15: C15.1 225,680.12 v2(300,680.12)
  Bottom Layer w15: v2(300,680.12) 402.24,680.12 v1(417.13,695) C16.2
NetLD1_1: LD1.1 R3.2 | length 48.8
  Top Layer w6: R3.2 LD1.1
NetLD2_1: LD2.1 R4.1 | length 48.8
  Top Layer w6: R4.1 LD2.1
NetLD3_1: LD3.1 R6.1 | length 48.8
  Top Layer w6: R6.1 LD3.1
NetLD4_1: LD4.1 R23.1 | length 48.8
  Top Layer w6: R23.1 LD4.1
NetLD5_1: LD5.1 R24.1 | length 58.8
  Top Layer w5.98: LD5.1 R24.1@350.32,345
NetLD6_1: LD6.1 R25.2 | length 58.9
  Top Layer w5.98: LD6.1 291.65,395.16 R25.2
NetQ1_1: Q1.1 R26.1 | length 399.9
  Bottom Layer w5.98: Q1.1 423.58,185 505,185 525,205 525,350 555.16,380.16 R26.1
NetQ1_3: Q1.3 R24.2 | length 199.7
  Top Layer w5.98: R24.2 389.84,345 v1(425,345)
  Bottom Layer w5.98: Q1.3 366.18,236.18 425,295 v1(425,345)
NetQ2_1: Q2.1 R27.1 | length 246.3
  Bottom Layer w5.98: Q2.1 550,161.42 550,325 565,340 580.16,340 R27.1@585.32,345.16
NetQ2_3: Q2.3 R25.1 | length 219.1
  Top Layer w5.98: R25.1 389.84,395 v1(425,395)
  Bottom Layer w5.98: v1(425,395) 485,335 Q2.3
NetR5_2: R5.2 U1.32 | length 162.5
  Top Layer w6: R5.2 950,435 1006.89,491.89 U1.32
NetR10_2: R10.2 U2.25 | length 129.5
  Top Layer w6: R10.2 270,750 279.65,740.35 U2.25
NetR12_2: R12.2 U2.24 | length 104.3
  Top Layer w6: R12.2 270,790 290.12,769.88 U2.24
NetR18_1: R18.1 U4.4 U7.3 | length 284.3
  Bottom Layer w6: U7.3 779.72,470.72 804,495 R18.1 865.32,470.31 878.03,457.6 U4.4
OUT_RTS: J1.5 U6.6 | length 453.8
  Top Layer w5.98: v1(1595,285) 1595,310 1615,330 v1(1710,330)
  Bottom Layer w5.98: v1(1595,285) 1595.63,285.63 U6.6 ; v1(1710,330) 1730,330 1760,360 1760,410 1785,435 1846.42,435 J1.5
OUT_TXD: J1.4 U6.3 | length 331
  Top Layer w5.98: v1(1645,285) v1(1705,285)
  Bottom Layer w5.98: v1(1645,285) 1654.68,294.69 U6.3 ; v1(1705,285) 1710,285 1780,355 1845.16,355 J1.4
PB_04: U1.24 U2.5 | length 869
  Top Layer w6: U2.5 542.87,832.87 585,875 585,930 615,960 715,960 780,895 780,710 872.13,617.87 U1.24
PB_05: R7.2 U1.25 U2.4 | length 915.8
  Top Layer w6: U2.4 557.13,817.13 v1(570,830) 600,860 600,925 620,945 710,945 765,890 765,705 867.87,602.13 U1.25
  Bottom Layer w6: R7.2 v1(570,830)
PB_06: U1.16 U2.15 | length 952.9
  Top Layer w6: v1(380,955) 385.63,949.37 U2.15 ; v1(1080,850) 1080,818.26 1091.89,806.37 U1.16
  Bottom Layer w6: v1(380,955) 380,1005 395,1020 655,1020 815,860 1070,860 v1(1080,850)
PB_07: U1.17 U2.14 | length 1094.5
  Top Layer w6: U2.14 401.38,978.62 385,995 385,1120 400,1135 505,1135 590,1050 745,1050 965,830 965,755 991.89,728.11 U1.17
PB_09: U1.19 U2.10 | length 900.1
  Top Layer w6: U2.10 464.37,944.37 490,970 525,970 590,1035 740,1035 855,920 855,735 893.39,696.61 U1.19
PB_10: U1.20 U2.9 | length 875.9
  Top Layer w6: U2.9 480.12,940.12 495,955 530,955 595,1020 735,1020 840,915 840,730 889.13,680.87 U1.20
PB_11: U1.21 U2.8 | length 867.1
  Top Layer w6: U2.8 530.12,880.12 540,890 540,945 600,1005 730,1005 825,910 825,725 884.88,665.12 U1.21
PB_12: U1.22 U2.7 | length 867.7
  Top Layer w6: U2.7 534.37,864.37 555,885 555,940 605,990 725,990 810,905 810,720 880.63,649.37 U1.22
PB_13: U1.23 U2.6 | length 868.4
  Top Layer w6: U2.6 538.62,848.62 570,880 570,935 610,975 720,975 795,900 795,715 876.38,633.62 U1.23
PB_14: R11.1 U1.26 U2.23 | length 1300.1
  Top Layer w6: R11.1 v1(275,830) 275,805 294.37,785.63 U2.23 U2.23@338.43,787.55 ; U1.26 1081.38,586.38 1095,600 v1(1095,665)
  Bottom Layer w6: v1(275,830) 275,805 255,785 255,665 280,640 475,640 515,680 1015,680 1030,665 v1(1095,665)
PB_15: U1.27 U2.22 | length 1236.8
  Top Layer w6: v1(300,810) 308.62,801.38 U2.22 ; U1.27 1085.63,570.63 1115,600 v1(1115,685)
  Bottom Layer w6: v1(300,810) 270,780 270,670 285,655 470,655 510,695 1025,695 1035,685 v1(1115,685)
PD_00: U1.11 U2.20 | length 1413.4
  Top Layer w6: v1(250,975) 250,890 307.13,832.87 U2.20 ; U1.11 1170.63,806.65 1180,816.02 v1(1180,825)
  Bottom Layer w6: v1(250,975) 250,1035 310,1095 680,1095 840,935 1130,935 1180,885 v1(1180,825)
PD_01: U1.12 U2.19 | length 1329.8
  Top Layer w6: v1(270,955) 270,890 311.38,848.62 U2.19 ; U1.12 1154.88,809.88 1160,815 v1(1160,850)
  Bottom Layer w6: v1(270,955) 270,1035 315,1080 675,1080 835,920 1120,920 1160,880 v1(1160,850)
PD_02: U1.13 U2.18 | length 1246.1
  Top Layer w6: v1(290,975) 290,890 315.63,864.37 U2.18 ; U1.13 1139.13,824.13 v1(1140,825)
  Bottom Layer w6: v1(290,975) 290,1035 320,1065 670,1065 830,905 1110,905 1140,875 v1(1140,825)
PD_03: U1.14 U2.17 | length 1165.3
  Top Layer w6: v1(310,955) 310,890 319.88,880.12 U2.17 ; v1(1120,850) 1120,815 1123.39,811.61 U1.14
  Bottom Layer w6: v1(310,955) 310,1035 325,1050 665,1050 825,890 1100,890 1120,870 v1(1120,850)
PD_04: U1.15 U2.16 | length 1027
  Top Layer w6: v1(355,975) 355,950 369.88,935.12 U2.16 ; v1(1100,825) 1107.64,817.36 U1.15
  Bottom Layer w6: v1(355,975) 355,1020 370,1035 660,1035 820,875 1085,875 1100,860 v1(1100,825)
PHY_AD0: J3.8 R9.2 U1.29 U2.11 | length 2098.9
  Top Layer w6: U2.11 448.62,948.62 490,990 v1(490,1000) R9.2 ; U1.29 1075.13,539.13 1135,599 v1(1135,665)
  Bottom Layer w5.98: J3.8 105.13,688.17 211.83,688.17 275,625 480,625 520,665 1005,665 1025,645 1115,645 v1(1135,665)
  Bottom Layer w6: J3.8 133.66,708.66 145,720 145,875 175,905 470,905 490,925 v1(490,1000)
PHY_AD3: J3.10 R8.2 U2.12 | length 583.9
  Top Layer w6: U2.12 432.87,952.87 450,970 v1(450,1000.16) R8.2
  Bottom Layer w6: J3.10 111.14,866.14 165,920 430,920 450,940 v1(450,1000.16)
RESETN: J4.4 J5.5 R31.1 U1.28 U2.32 U3.3 U7.2 | length 2163.9
  Top Layer w5.98: v1(719,220) 719,474 785,540 v1(785,561) ; v1(980,573.5) 998.62,554.88 U1.28
  Top Layer w6: U2.32 564.65,740.35 613,692 613,591 643,561 v1(785,561)
  Bottom Layer w5.98: v1(719,220) U3.3@845.39,220 ; v1(785,561) 784.72,561.28 U7.2 743.4,614.84 938.66,614.84 v1(980,573.5) 980,575 1017,612 1213,612 1242.13,641.13 1242.13,847.87 1175,915 1175,1050 J5.5 ; U3.3 U3.3@845.39,220 ; U3.3@850.39,225 U3.3@845.39,220
SCL1: R16.1 U1.57 U5.1 | length 650.4
  Top Layer w6: U1.57 1437.13,617.87 1445,610 1445,375 1557.68,262.32 1557.68,187.72 U5.1 v1(1515.32,187.4)
  Bottom Layer w6: v1(1515.32,187.4) 1578.03,187.4 R16.1
SDA1: R15.1 U1.58 U5.3 | length 798.7
  Top Layer w6: U1.58 1441.38,633.62 1460,615 1460,380 1600,240 1600,119.69 1592.91,112.6 U5.3 v1(1515.32,112.6)
  Bottom Layer w6: v1(1515.32,112.6) 1578.03,112.6 R15.1
SPI_MISO1: U1.47 U3.8 | length 572.7
  Top Layer w6: U1.47 1312.36,382.36 1310,380 1310,365 v1(1330,345)
  Bottom Layer w6: U3.8 1115,120 1095,140 1095,280 1115,300 1285,300 v1(1330,345)
SPI_MOSI1: U1.48 U3.1 | length 745.5
  Top Layer w6: U1.48 1328.11,376.89 v1(1330,375)
  Bottom Layer w5.98: 955,290 955,295 980,320
  Bottom Layer w6: U3.1 935,120 955,140 955,290 ; 980,320 1275,320 v1(1330,375)
SPI_SCLK1: U1.46 U3.2 | length 655.4
  Top Layer w6: v1(1290,375) 1296.61,381.61 U1.46
  Bottom Layer w6: U3.2 920,170 940,190 940,295 ; 940,300 975,335 1250,335 v1(1290,375)
SPI_SSEL1: R13.1 U1.45 U3.4 | length 697
  Top Layer w6: v1(1270,395) 1280.87,405.87 U1.45 1280.87,584.45 v1(1280.32,585)
  Bottom Layer w5.98: U3.4 890,270 920,300
  Bottom Layer w6: 920,300 970,350 1235,350 1270,385 v1(1270,395) ; v1(1280.32,585) R13.1
STATUS: J1.12 LD4.2 U1.35 | length 1671.9
  Top Layer w6: v1(1180,570) 1160,570 1123.39,533.39 U1.35 1123.39,381.61 1215,290 1420,290 1431.5,278.5 LD4.2
  Bottom Layer w5.98: 1256.77,570 1271.77,555 1555,555 1675,675
  Bottom Layer w6: v1(1180,570) 1256.77,570 ; 1675,675 1675,965 1694.25,984.25 1844.49,984.25 J1.12
STATUS_LED0: J2.2 LD2.2 U1.1 | length 1530.5
  Top Layer w6: U1.1 1328.11,813.11 1340,825 1415,825 1470,880 1660,880 1675,865 1675,485 1745,415 1745,285 1793.78,236.22 J2.2 ; LD2.2 v1(1470,145)
  Bottom Layer w6: v1(1470,145) 1490,165 1490,200 1506.22,216.22 J2.2@1805.12,216.22
STATUS_LED1: J2.3 LD3.2 U1.2 | length 1496.9
  Top Layer w6: U1.2 1312.36,817.36 1335,840 1410,840 1465,895 1665,895 1690,870 1690,490 1760,420 1760,355 1800.04,314.96 J2.3 ; LD3.2 v1(1470,200)
  Bottom Layer w6: v1(1470,200) 1470,215 1485,230 1720.16,230 J2.3
SWCLK: J4.3 U1.49 | length 571.1
  Top Layer w6: v1(1270,685) 1270,630 1310,590 1310,515 1333.11,491.89 U1.49
  Bottom Layer w6: J4.3 1225,890 1270,845 v1(1270,685)
SWDIO: J4.2 U1.50 | length 532.2
  Top Layer w6: v1(1290,705) 1290,630 1325,595 1325,520 1337.36,507.64 U1.50
  Bottom Layer w6: J4.2 1275,865 1290,850 v1(1290,705)
U_CTS0: U1.40 U6.11 | length 537.3
  Top Layer w6: U1.40 v1(1202.13,495)
  Bottom Layer w5.98: 1263.1,518.1 1621.9,518.1 1635,505 U6.11@1635,466.93
  Bottom Layer w6: v1(1202.13,495) 1225.23,518.1 1263.1,518.1
U_DSR0: J1.10 U1.37 | length 1028.7
  Top Layer w6: U1.37 1154.88,489.88 v1(1160,495)
  Bottom Layer w5.98: 1545,530 1570,530 1705,665
  Bottom Layer w6: v1(1160,495) 1160,515 1175,530 1220.29,530 1268.03,530.01 1545,530 ; 1705,665 1705,811.77 1720,826.77 1844.49,826.77 J1.10
U_DTR0: J1.6 U1.38 | length 992.4
  Top Layer w6: v1(1165,395) 1170.63,400.63 U1.38 ; v1(1560,320) 1585,345 1670,345 v1(1720,395)
  Bottom Layer w6: v1(1165,395) 1165,430 1181.9,446.9 1386.76,446.9 1513.66,320 v1(1560,320) ; v1(1720,395) 1760,435 1760,490 1780,510 1842.68,510 J1.6
U_RTS0: U1.41 U6.5 | length 682.9
  Top Layer w6: v1(1210,395) 1217.87,402.87 U1.41
  Bottom Layer w5.98: 1223.07,433.07 1381.93,433.07 1410,405 1410,300 1450,260 1605,260 1615.31,270.31 U6.5
  Bottom Layer w6: v1(1210,395) 1210,420 1223.07,433.07
U_RXD0: R26.2 U1.43 U6.8 | length 1071.6
  Top Layer w6: U1.43 v1(1249.37,495)
  Bottom Layer w5.98: R26.2 624.84,380 1090,380 1175,465 1219.37,465 v1(1249.37,495) ; 1290,465 1475,465 1515.47,424.53 U6.8
  Bottom Layer w6: v1(1249.37,495) 1260,495 1290,465
U_RXD2: J2.6 J5.4 U1.4 | length 1266.7
  Top Layer w6: U1.4 1280.87,825.87 1325,870 1400,870 1465,935 v1(1555,935) 1665,935 1720,880 1720,575 1743.82,551.18 J2.6
  Bottom Layer w6: J5.4 1455,970 1540,970 1555,955 v1(1555,935)
U_TXD0: R27.2 U1.42 U6.2 | length 1356.6
  Top Layer w6: U1.42 1233.62,401.38 v1(1240,395)
  Bottom Layer w5.98: R27.2@624.68,345.16 629.84,340 930,340 955,365 1225,365 1240,380 v1(1240,395) ; 1250,420 1375,420 1395,400 1395,295 1445,245 1650,245 1674.37,269.37 U6.2
  Bottom Layer w6: v1(1240,395) 1240,410 1250,420
U_TXD2: J2.5 J5.3 U1.3 | length 1304.1
  Top Layer w6: U1.3 1296.61,821.61 1330,855 1405,855 1465,915 v1(1575,915) 1665,915 1705,875 1705,495 1727.56,472.44 J2.5
  Bottom Layer w6: J5.3 1425,1020 1460,985 1560,985 1575,970 v1(1575,915)
VCC_3.3V: C1.1 C2.2 C5.1 C6.2 C13.2 C17.1 C18.2 C19.2 C21.1 C22.1 J1.1 J3.12 J4.1 J5.1 L2.1 Q1.2 Q2.2 R3.1 R4.2 R6.2 R13.2 R14.2 R15.2 R16.2 R23.2 R28.2 R31.2 U1.10 U1.61 U3.5 U3.6 U4.5 U5.4 U6.14 U7.4 | length 1615.3
  Top Layer w8: v1(1175.32,725) 1186.38,736.06 U1.10
  Top Layer w9: v1(1325,665.32) 1340.55,680.87 U1.61
  Top Layer w15: v1(885,830) 885,794.84 R28.2 ; C18.2 905,574.69 R14.2 938.35,534.69 v2(940.32,532.72) ; v2(1245,244.69) 1255.32,255 R23.2 ; v1(1250,90) R3.1 ; v1(1250,145) R4.2 ; v1(1250,200) R6.2 ; U5.4 v1(1685.32,112.6)
  Top Layer w20: C1.1 v2(1525,590)
  Bottom Layer w5.98: U6.14 1729.53,424.53 1740,435 v1(1740,500) 1740,514.53 C21.1
  Bottom Layer w6: U7.4 715,517.13 715,611.16 R31.2
  Bottom Layer w10: v1(626,431) 636.84,420.16 C22.1 668.32,470.44 U7.4
  Bottom Layer w15: Q1.2 297.6,82.4 320,60 v2(370,60) 425,60 447.6,82.6 Q2.2 ; v2@940.32,532.4 U4.5 ; U3.6 1185,220 1190,215 1209.68,215 C17.1 ; U3.5 1195,270 1210,255 C17.1 ; v1(1175.32,725) C6.2 ; v2(1245,244.69) 1245,235 1224.68,214.69 C17.1 ; R13.2 v1(1319.68,635) ; v1(1325,665.32) C2.2 ; R16.2 C19.2 R15.2 1655.32,110 1657.91,112.6 v1(1685.32,112.6)
  other v2: 1050,970 1050,1010
XIN: C4.2 R1.2 U1.63 Y1.3 | length 339.6
  Top Layer w5.98: R1.2 1594.68,755.32
  Top Layer w6: U1.63 1417.36,712.36 1460.32,755.32 R1.2 ; C4.2 1594.68,703.82 Y1.3 1604.53,745.47 1594.68,755.32
XOUT: C3.2 R1.1 U1.64 Y1.1 | length 255.1
  Top Layer w5.98: R1.1 1543.82,794.68 Y1.1 1555.32,806.18 C3.2
  Top Layer w6: U1.64 1413.11,728.11 1479.68,794.68 R1.1
XTAL1: C7.2 U2.2 Y2.1 | length 299.4
  Top Layer w6: U2.2 694.37,785.63 704.53,775.47 Y2.1 694.68,743.66 C7.2
XTAL2: C8.2 U2.3 Y2.3 | length 229.3
  Top Layer w6: U2.3 645.47,801.38 Y2.3 655.32,826.34 C8.2
pads on no net: J3.1 J3.9 J3.11 U1.30 U1.31 U1.33 U1.34 U1.44 U1.51 U1.52 U1.53 U1.54 U1.55 U1.56 U1.59 U1.60 U2.1 U2.21 U4.1

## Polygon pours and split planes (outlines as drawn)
VCC_3.3V on Top Layer "Top Layer-NET" (solid, remove dead copper, pour order 20): 975,1030 965,1020 965,960 975,950 1060,950 1070,960 1070,1020 1060,1030
IP_3.3V on Top Layer "Top Layer-NET" (solid, remove dead copper, pour order 14): 945,1030 955,1020 955,960 945,950 860,950 850,960 850,1020 860,1030 920,1030
GND on Top Layer "Top Layer-net" (solid, remove dead copper, pour order 10): 35,1181.1 0,1181.1 0,1035 0,0 1790,0 1968.5,0 1968.5,205 1968.5,1181.1 40,1181.1
VCC_3.3V on Bottom Layer "Top Layer-NET" (solid, remove dead copper, pour order 18): 1015,1035 985,1035 975,1025 975,960 985,950 1060,950 1070,960 1070,1025 1060,1035
IP_3.3V on Bottom Layer "Top Layer-NET" (solid, remove dead copper, pour order 16): 935,1035 860,1035 850,1025 850,960 860,950 935,950 945,960 945,1025
GND on Bottom Layer "Top Layer-net" (solid, remove dead copper, pour order 12): 70,1181.1 0,1181.1 0,1095 0,0 215,0 1968.5,0 1968.5,170 1968.5,1181.1 75,1181.1
GND on Internal Plane 1 (split plane): 1941.09,1160.75 1943.5,1159.75 1945.56,1158.16 1947.15,1156.1 1948.15,1153.69 1948.44,1151.46 1948.41,1151.1 1948.41,30 1948.44,29.64 1948.15,27.42 1947.15,25.01 1945.56,22.94 1943.5,21.35 1941.09,20.35 1938.86,20.06 1938.5,20.1 30,20.1 29.64,20.06 27.42,20.35 25.01,21.35 22.94,22.94 21.35,25.01 20.35,27.42 20.06,29.64 20.1,30 20.1,1151.1 20.06,1151.46 20.35,1153.69 21.35,1156.1 22.94,1158.16 25.01,1159.75 27.42,1160.75 29.64,1161.04 30,1161.01 1938.5,1161.01 1938.86,1161.04
IP_3.3V on Internal Plane 2 (split plane): 949.91,1106.4 899.01,1106.4 899.01,949 949.91,949 949.91,905.09 800,905.09 797.39,904.74 794.96,903.74 792.87,902.13 791.26,900.04 790.26,897.61 789.91,895 789.91,530.09 155.09,530.09 155.09,1161.01 949.91,1161.01
VCC_3.3V on Internal Plane 2 (split plane): 1941.09,1160.75 1943.5,1159.75 1945.56,1158.16 1947.15,1156.1 1948.15,1153.69 1948.44,1151.46 1948.41,1151.1 1948.41,30 1948.44,29.64 1948.15,27.42 1947.15,25.01 1945.56,22.94 1943.5,21.35 1941.09,20.35 1938.86,20.06 1938.5,20.1 30,20.1 29.64,20.06 27.42,20.35 25.01,21.35 22.94,22.94 21.35,25.01 20.35,27.42 20.06,29.64 20.1,30 20.1,1151.1 20.06,1151.46 20.35,1153.69 21.35,1156.1 22.94,1158.16 25.01,1159.75 27.42,1160.75 29.64,1161.04 30,1161.01 134.91,1161.01 134.91,520 135.26,517.39 136.26,514.96 137.87,512.87 139.96,511.26 142.39,510.26 145,509.91 800,509.91 802.61,510.26 805.04,511.26 807.13,512.87 808.74,514.96 809.74,517.39 810.09,520 810.09,884.91 960,884.91 962.61,885.26 965.04,886.26 967.13,887.87 968.74,889.96 969.74,892.39 970.09,895 970.09,949 1021,949 1021,1159.81 970.09,1159.81 970.09,1161.01 1938.5,1161.01 1938.86,1161.04

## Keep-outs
Keep-Out Layer:
  the board outline again, w5
  text ".Layer_Name" at 370,1250 h60

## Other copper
Top Layer:
  pour cut-out: 400.59,1166.34 405.51,1161.42 405.51,1154.53 401.57,1150.59 404.53,1150.59 504.92,1150.59 501.97,1153.54 501.97,1161.42 506.89,1166.34
  pour cut-out: 900.59,843.5 900.59,847.44 912.4,859.25 917.39,859.25 918.31,853.35 911.48,853.35 906.53,848.39 904.53,843.5
  pour cut-out: 1627.95,134.84 1615.16,147.64 1615.16,134.84
  pour cut-out: 1763.78,238.19 1763.78,243.11 1761.81,243.11 1762.63,238.19
  pour cut-out: 1722.44,268.7 1723.42,268.7 1726.38,269.69 1733.27,269.69 1738.19,268.7 1738.19,273.62 1722.44,273.62
  pour cut-out: 1610.24,252.95 1610.24,261.81 1614.17,265.75 1632.87,265.75 1632.87,274.61 1610.24,274.61 1598.43,274.61 1598.43,252.95
  pour cut-out: 814.96,13.78 821.85,20.67 821.85,30.51 817.91,34.45 823.82,34.45 1957.68,34.45 1957.68,13.78
  pour cut-out: 633.86,866.14 633.86,879.92 626.97,873.03 620.08,873.03 615.16,877.95 615.16,866.14
  pour cut-out: 718.5,697.83 723.43,702.76 718.5,702.76
  pour cut-out: 538.39,753.94 538.39,771.65 569.88,771.65 563.98,765.75 563.97,759.84 569.88,753.94
  pour cut-out: 1073.82,745.57 1065.45,745.57 1073.82,753.94
  pour cut-out: 1073.94,465.43 1065.43,473.94 1073.94,473.94
  pour cut-out: 1107.28,393.7 1098.92,402.07 1107.28,402.07
  pour cut-out: 1415.35,687.99 1425.2,697.83 1415.35,697.83
  pour cut-out: 1428.15,647.64 1416.34,659.45 1416.34,647.64
  pour cut-out: 1648.62,525.59 1658.46,515.75 1664.37,515.75 1664.37,525.59
  pour cut-out: 1693.9,392.72 1693.88,405.5 1693.9,439.96 1693.9,443.9 1710.63,443.9 1710.63,392.72
  pour cut-out: 936.53,419.72 928.03,411.22 928.03,419.72
  pour cut-out: 521.65,582.68 541.34,582.68 535.43,576.77 535.43,565.94 521.65,565.94
  pour cut-out: 1573.82,505.91 1573.82,488.19 1566.93,488.19 1562.01,483.27 1562.01,488.19 1562.01,509.84 1565.94,505.9
  pour cut-out: 1765.75,157.48 ccw(c1805.12,157.48) 1805.12,118.11 ccw(c1805.12,157.48) 1844.49,157.48 ccw(c1805.12,157.48) 1805.12,196.85 ccw(c1805.12,157.48)
  pour cut-out: 1844.49,314.96 ccw(c1883.86,314.96) 1883.86,275.59 ccw(c1883.86,314.96) 1923.23,314.96 ccw(c1883.86,314.96) 1883.86,354.33 ccw(c1883.86,314.96)
  pour cut-out: 1844.49,629.92 ccw(c1883.86,629.92) 1883.86,590.55 ccw(c1883.86,629.92) 1923.23,629.92 ccw(c1883.86,629.92) 1883.86,669.29 ccw(c1883.86,629.92)
  pour cut-out: 1844.49,944.88 ccw(c1883.86,944.88) 1883.86,905.51 ccw(c1883.86,944.88) 1923.23,944.88 ccw(c1883.86,944.88) 1883.86,984.25 ccw(c1883.86,944.88)
  pour cut-out: 1765.75,1023.62 ccw(c1805.12,1023.62) 1805.12,984.25 ccw(c1805.12,1023.62) 1844.49,1023.62 ccw(c1805.12,1023.62) 1805.12,1062.99 ccw(c1805.12,1023.62)
  pour cut-out: 45.28,393.7 ccw(c84.65,393.7) 84.65,354.33 ccw(c84.65,393.7) 124.02,393.7 ccw(c84.65,393.7) 84.65,433.07 ccw(c84.65,393.7)
  pour cut-out: 45.28,629.92 ccw(c84.65,629.92) 84.65,590.55 ccw(c84.65,629.92) 124.02,629.92 ccw(c84.65,629.92) 84.65,669.29 ccw(c84.65,629.92)
  pour cut-out: 1085.63,1100 ccw(c1125,1100) 1125,1060.63 ccw(c1125,1100) 1164.37,1100 ccw(c1125,1100) 1125,1139.37 ccw(c1125,1100)
  pour cut-out: 1085.63,975 ccw(c1125,975) 1125,935.63 ccw(c1125,975) 1164.37,975 ccw(c1125,975) 1125,1014.37 ccw(c1125,975)
  text ".Layer_Name" at 370,1250 h60
Bottom Layer:
  pour cut-out: 254.92,603.35 254.92,622.05 265.75,622.05 265.75,603.35
  pour cut-out: 240.16,935.04 245.08,939.96 245.08,948.82 240.16,953.74 251.97,953.74 251.97,935.04
  pour cut-out: 508.86,903.54 512.91,903.54 512.91,907.6 508.86,911.65 508.84,987.2 499.01,987.2 499.02,903.54
  pour cut-out: 160.43,935.04 154.53,925.2 119.09,931.1 118.11,931.1 118.11,944.88 129.92,933.07 144.68,930.12
  pour cut-out: 1344.49,586.61 1344.49,575.79 1347.44,572.84 1353.35,572.83 1353.35,568.9 1341.54,568.9 1341.54,586.61
  pour cut-out: 1260.83,108.27 1260.83,187.01 1238.19,187.01 1238.19,108.27
  pour cut-out: 1669.29,512.8 1669.29,537.4 1661.42,537.4 1661.42,512.8
  pour cut-out: 404.53,407.07 404.53,414.37 398.62,420.28 396.66,421.26 396.66,422.25 405.51,431.1 409.45,431.1 410.43,427.17 417.32,420.28 421.42,419.13
  pour cut-out: 368.6,423.23 381.4,423.23 381.4,429.13 368.6,429.13
  pour cut-out: 1339.57,403.54 1380.91,403.54 1380.91,320.86 1372.05,329.73 1350.39,329.73 1347.44,326.77 1339.57,326.77
  pour cut-out: 1267.72,263.78 1259.84,271.65 1259.84,279.53 1270.67,290.35 1216.54,290.35 1216.54,263.78
  pour cut-out: 1642.72,191.93 1651.57,200.79 1642.72,200.79
  pour cut-out: 1071.85,948.82 1071.85,1008.86 1080.71,1000 1098.43,1000 1102.36,1003.94 1102.36,948.82
  pour cut-out: 1480.32,124.02 1480.32,123.03 1483.27,123.03 1490.16,123.03 1496.06,117.13 1515.32,138.09 1510.54,138.09 1503.94,144.69 1503.94,153.54 1511.81,161.42 1522.63,161.42 1527.56,166.34 1503.94,166.34 1503.94,160.43 1480.31,134.85
  pour cut-out: 1769.68,549.68 1762.25,551.18 1762.45,549.68 1753.93,549.69 1753.94,516.73 1769.68,516.73
  pour cut-out: 1674.21,409.45 1706.69,409.45 1706.69,376.97 1703.03,376.97 1701.77,376.97 1700.79,377.95 1699.8,378.94 1698.82,379.92 1695.87,382.87 1693.9,384.84 1693.9,401.57 1691.93,403.54 1674.21,403.54
  pour cut-out: 1679.13,362.2 1719.49,362.2 1721.46,364.17 1721.46,368.11 1719.49,370.08 1701.77,370.08 1701.77,378.94 1719.49,378.94 1744.09,378.94 1744.09,362.2 1744.09,349.41 1679.13,349.41
  pour cut-out: 1545,338.58 1545,350 1558.19,363.19 1595.79,363.19 1587.86,338.58
  region net GND: 1580,360 1575,360 1550,360 1545,355 1515,355 1510,360 1510,380 1515,385 1535,385 1550,370 1580,370
  pour cut-out: 1108.27,469.49 1141.73,469.49 1144.69,466.54 1144.68,457.68 1145.67,456.69 1158.46,456.69 1158.46,488.19 1108.27,488.19
  pour cut-out: 1844.49,157.48 cw(c1805.12,157.48) 1805.12,118.11 cw(c1805.12,157.48) 1765.75,157.48 cw(c1805.12,157.48) 1805.12,196.85 cw(c1805.12,157.48)
  pour cut-out: 1923.23,314.96 cw(c1883.86,314.96) 1883.86,275.59 cw(c1883.86,314.96) 1844.49,314.96 cw(c1883.86,314.96) 1883.86,354.33 cw(c1883.86,314.96)
  pour cut-out: 1923.23,629.92 cw(c1883.86,629.92) 1883.86,590.55 cw(c1883.86,629.92) 1844.49,629.92 cw(c1883.86,629.92) 1883.86,669.29 cw(c1883.86,629.92)
  pour cut-out: 1923.23,944.88 cw(c1883.86,944.88) 1883.86,905.51 cw(c1883.86,944.88) 1844.49,944.88 cw(c1883.86,944.88) 1883.86,984.25 cw(c1883.86,944.88)
  pour cut-out: 1844.49,1023.62 cw(c1805.12,1023.62) 1805.12,984.25 cw(c1805.12,1023.62) 1765.75,1023.62 cw(c1805.12,1023.62) 1805.12,1062.99 cw(c1805.12,1023.62)
  pour cut-out: 124.02,393.7 cw(c84.65,393.7) 84.65,354.33 cw(c84.65,393.7) 45.28,393.7 cw(c84.65,393.7) 84.65,433.07 cw(c84.65,393.7)
  pour cut-out: 124.02,629.92 cw(c84.65,629.92) 84.65,590.55 cw(c84.65,629.92) 45.28,629.92 cw(c84.65,629.92) 84.65,669.29 cw(c84.65,629.92)
  pour cut-out: 1164.37,1100 cw(c1125,1100) 1125,1060.63 cw(c1125,1100) 1085.63,1100 cw(c1125,1100) 1125,1139.37 cw(c1125,1100)
  pour cut-out: 1164.37,975 cw(c1125,975) 1125,935.63 cw(c1125,975) 1085.63,975 cw(c1125,975) 1125,1014.37 cw(c1125,975)
  text ".Layer_Name" at 370,1250 h60
Internal Plane 1 (plane layer: these items are gaps in the copper):
  pour cut-out: 1033.46,980.32 1033.46,998.03 1034.45,998.03 1063.98,998.03 1063.98,980.32
  pour cut-out: 854.33,980.32 854.33,998.03 855.31,998.03 884.84,998.03 884.84,980.32
  text "GND" at 370,1251.26 h60
Internal Plane 2 (plane layer: these items are gaps in the copper):
  pour cut-out: 572.83,475.39 597.44,475.39 597.44,451.77 572.83,451.77
  pour cut-out: 389.76,860.24 389.76,790.35 461.61,790.35 461.61,860.24
  lines w20: 145,1181.1 145,520 800,520 800,895 960,895 960,1181.1
  text "POWER" at 370,1251.26 h60
  text "IP_3.3V" at 935,955 h30 r90
  text "VCC_3.3V" at 1005,955 h30 r90

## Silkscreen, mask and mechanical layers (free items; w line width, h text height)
Top Overlay:
  rectangle: 135.38,12.41 1159,288
  lines w5: 1948.48,-0.36 ccw(c1949.23,10.39) 1960,10 ; 5,10 ccw(c15,10) 15,0 1950,0 1955,5 ; 5,10 1960,10 ; 5,10 10,5 1955,5 ; 1955,5 1960,10
  text ".Layer_Name" at 370,1251.26 h60
  text "SWD" at 1360,940 h50
  text "W7500" at 1145,880 h50
  text "10" at 1710,855 h25
  text "9" at 140,775 h25
  text "5" at 140,460 h25
  text "5" at 1730,460 h25
  text "UART0" at 200,427 h50
  text "Tx" at 144,380 h50
  text "Rx" at 145,332 h50
  text "WIZ750SR-100 Ver1.1" at 635.83,299.21 h60
Bottom Overlay:
  lines w7.87: 241,1105 680,1105 ; 305,1005 680,1005 ; 310,1055 680,1055
  text ".Layer_Name" at 370,1250 h60
  text "5" at 1212.56,1144.65 h25 r270
  text "WIZ750SR-100" at 680,1115 h47.24
  text "http://wiznet.io" at 680,1070 h39.37
  text "GND" at 1155,1025 h25
  text "RSTN" at 1265,1025 h25
  text "RXD" at 1355,1025 h25
  text "TXD" at 1455,1025 h25
  text "BOOT" at 1565,1025 h25
  text "3.3V" at 1665,1025 h25
  text "Designed by WIZnet" at 680,1020 h39.37
  text "10" at 1745,855 h25
  text "10" at 175,850 h25
  text "5" at 160,460 h25
  text "5" at 1745,460 h25
  text "1" at 150,145 h25
  text "1" at 1740.32,120 h25
Top Paste:
  text ".Layer_Name" at 370,1250 h60
Bottom Paste:
  text ".Layer_Name" at 370,1250 h60
Top Solder:
  text ".Layer_Name" at 370,1250 h60
Bottom Solder:
  text ".Layer_Name" at 370,1250 h60
Drill Guide:
  text ".Layer_Name" at 370,1250 h60
Mechanical 2:
  lines w5: 2143,475 3173,475 ; 2143,585 3173,585 ; 0,30 ccw(c30,30) 30,0 1938.5,0 ccw(c1938.5,30) 1968.5,30 1968.5,1151.1 ccw(c1938.5,1151.1) 1938.5,1181.1 30,1181.1 ccw(c30,1151.1) 0,1151.1 0,30 ; 2090,28 ccw(c2118,28) 2118,0 3188,0 ccw(c3188,28) 3216,28 3216,785 ccw(c3188,785) 3188,813 2118,813 ccw(c2118,785) 2090,785 2090,28
  text "BOARD NAME : WIZ750SR-100" at 0,1690 h60
  text "VERSION : V1.1" at 0,1580 h60
  text "SIZE : 50mmX30mmX1.6T" at 0,1470 h60
  text "GERBER DATE : 2018.04.16" at 0,1360 h60
  text "LAYER :" at 0,1250 h60
  text "Layer Stack Up Detail for:" at 2148,730 h40
  text "WIZ750SR-100 V1.1.PcbDoc" at 2143,635 h50
  text "Layer Name : 4L  1.6T" at 2148,510 h40
  text "Top Layer" at 2143,365 h60
  text "GND" at 2143,255 h60
  text "POWER" at 2143,150 h60
  text "Bottom Layer" at 2143,50 h60
  text "KS Technology artwork" at 2090,-160 h200
Drill Drawing:
  text ".Layer_Name" at 370,1250 h60
  text ".Legend" at 2170,920 h40

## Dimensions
0,30 to 1968.5,30 on Mechanical 2
30,0 to 30,1181.1 on Mechanical 2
